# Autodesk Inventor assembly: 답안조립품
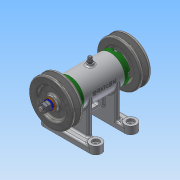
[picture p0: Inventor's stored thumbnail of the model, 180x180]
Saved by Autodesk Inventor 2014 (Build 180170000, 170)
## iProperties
Created: 2015-11
Part Number: 답안조립품
Document SubType Name: Assembly
Designer: 702
Author: 702
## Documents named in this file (15)
- C:\Users\702\Desktop\451109v1039\답안조립품.iam
- C:\Users\702\Desktop\451109v1039\1-본체.ipt
- C:\Users\702\Desktop\451109v1039\커버.ipt
- C:\Users\702\Desktop\451109v1039\오일 실 15 25 7.ipt
- C:\Users\702\Desktop\451109v1039\축.ipt
- C:\Users\702\Desktop\451109v1039\베어링 15 x 32 x 9.ipt
- C:\Users\702\Desktop\451109v1039\V벨트풀리.ipt
- C:\Users\702\Desktop\451109v1039\볼트 M4 x 12.ipt
- C:\Users\702\Desktop\451109v1039\키 3 x 3 x 12.ipt
- C:\Users\702\Desktop\451109v1039\와셔 8x17.ipt
- C:\Users\702\Desktop\451109v1039\스프링와셔 8.ipt
- C:\Users\702\Desktop\451109v1039\너트 M 8.ipt
- C:\Users\702\Desktop\451109v1039\니플 M 6 x 0.75.ipt
- C:\Users\702\Desktop\451109v1039\와셔 6x11.5.ipt
- C:\Users\702\Desktop\451109v1039\볼트 M 6 x 8.ipt
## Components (13 placed, 4 different names)
1. 1-본체:1
2. KS B 2023 6002 - 15 x 32 x 9:1
3. KS B 2023 6002 - 15 x 32 x 9:2
4. V벨트풀리:1
5. V벨트풀리:2
6. ISO 4762 M4 x 12:1
7. ISO 4762 M4 x 12:3
8. ISO 4762 M4 x 12:4
9. ISO 4762 M4 x 12:5
10. ISO 4762 M4 x 12:2
11. ISO 4762 M4 x 12:6
12. ISO 4762 M4 x 12:7
13. ISO 4762 M4 x 12:8
